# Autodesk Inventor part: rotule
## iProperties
Created: 2002-06
Part Number: rotule
Material: Par défaut
Document SubType Name: Modélisation
Designer: REVEST Pierre
Control State: 0
Master: False
Checked Out: False
Shininess: 100.0
Length Units: 11269
Angle Units: 11279
Time Units: 11290
Mass Units: 11283
Length Display Precision: 3
Angle Display Precision: 2
Density: 0.0
Volumn: 0.0
Area: 0.0
PropertySet Name: Model Information
Author: REVEST Pierre
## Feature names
1. Révolution1 [Revolution]
2. Chanfrein1 [Chamfer]
3. Extrusion3
4. Congé2 [Fillet]
5. Extrusion4
6. Congé3 [Fillet]
7. Révolution2 [Revolution]
